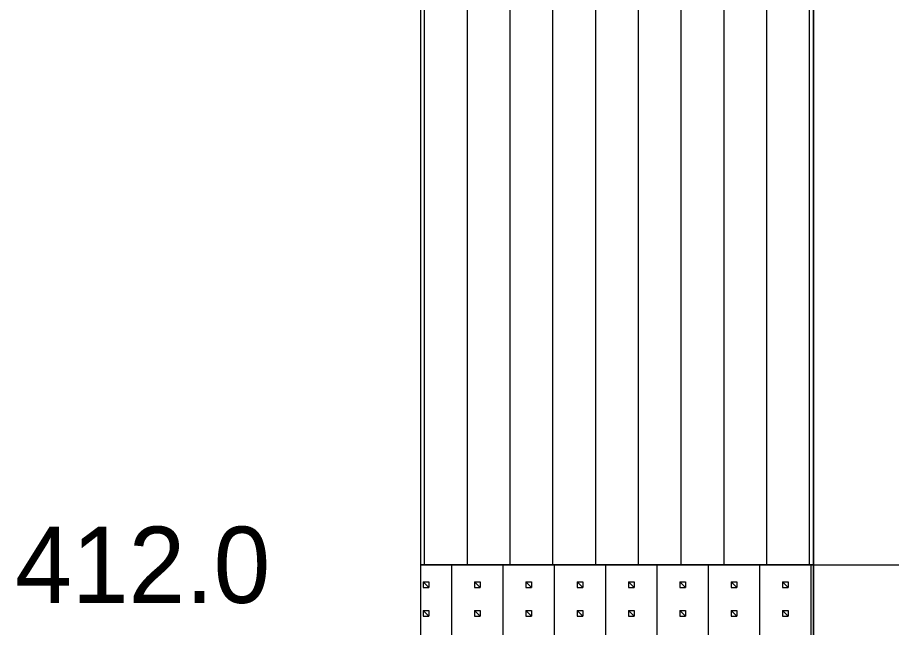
# Model space of a CAD drawing. Extents: x 9422 to 9552, y 6780 to 6860.
# Drawn here: x 9512.845 to 9515.399, y 6826.785 to 6828.568 of the extents above; entities that cross this region are included whole.
import ezdxf

# ---------------------------------------------------------------- set-up
doc = ezdxf.new("R2010")
doc.units = 0
doc.layers.add('7', color=7, linetype='Continuous')
doc.layers.add('8', color=7, linetype='Continuous')

msp = doc.modelspace()

# ---------------------------------------------------------------- linework, layer by layer
at = {"layer": '7'}
for p, q in [((9514.0232, 6831.9684), (9514.0232, 6826.9684)), ((9515.1715, 6826.9684), (9515.1715, 6831.9684)), ((9514.0232, 6826.9684), (9515.1715, 6826.9684)), ((9514.0232, 6826.9684), (9514.0232, 6825.1684)), ((9515.1715, 6826.9684), (9514.0232, 6826.9684)), ((9515.1715, 6825.1684), (9515.1715, 6826.9684)), ((9515.1715, 6826.9684), (9526.1141, 6826.9684))]:
    msp.add_line(p, q, dxfattribs=at)
for points in [[(9514.0232, 6850.4861), (9514.0232, 6821.9406)], [(9515.1715, 6850.4861), (9515.1715, 6821.9406)]]:
    msp.add_lwpolyline(points, dxfattribs=at)
at = {"layer": '8'}
for p, q in [((9514.0348, 6828.4684), (9514.0348, 6828.7184)), ((9514.1598, 6828.4684), (9514.1598, 6828.7184)), ((9514.2848, 6828.4684), (9514.2848, 6828.7184)), ((9514.4098, 6828.4684), (9514.4098, 6828.7184)), ((9514.5348, 6828.4684), (9514.5348, 6828.7184)), ((9514.6598, 6828.4684), (9514.6598, 6828.7184)), ((9514.7848, 6828.4684), (9514.7848, 6828.7184)), ((9514.9098, 6828.4684), (9514.9098, 6828.7184)), ((9515.0348, 6828.4684), (9515.0348, 6828.7184)), ((9515.1598, 6828.4684), (9515.1598, 6828.7184)), ((9514.0348, 6828.2184), (9514.0348, 6828.4684)), ((9514.1598, 6828.2184), (9514.1598, 6828.4684)), ((9514.2848, 6828.2184), (9514.2848, 6828.4684)), ((9514.4098, 6828.2184), (9514.4098, 6828.4684)), ((9514.5348, 6828.2184), (9514.5348, 6828.4684)), ((9514.6598, 6828.2184), (9514.6598, 6828.4684)), ((9514.7848, 6828.2184), (9514.7848, 6828.4684)), ((9514.9098, 6828.2184), (9514.9098, 6828.4684)), ((9515.0348, 6828.2184), (9515.0348, 6828.4684)), ((9515.1598, 6828.2184), (9515.1598, 6828.4684)), ((9514.0348, 6827.9684), (9514.0348, 6828.2184)), ((9514.1598, 6827.9684), (9514.1598, 6828.2184)), ((9514.2848, 6827.9684), (9514.2848, 6828.2184)), ((9514.4098, 6827.9684), (9514.4098, 6828.2184)), ((9514.5348, 6827.9684), (9514.5348, 6828.2184)), ((9514.6598, 6827.9684), (9514.6598, 6828.2184)), ((9514.7848, 6827.9684), (9514.7848, 6828.2184)), ((9514.9098, 6827.9684), (9514.9098, 6828.2184)), ((9515.0348, 6827.9684), (9515.0348, 6828.2184)), ((9515.1598, 6827.9684), (9515.1598, 6828.2184)), ((9514.0348, 6827.7184), (9514.0348, 6827.9684)), ((9514.1598, 6827.7184), (9514.1598, 6827.9684)), ((9514.2848, 6827.7184), (9514.2848, 6827.9684)), ((9514.4098, 6827.7184), (9514.4098, 6827.9684)), ((9514.5348, 6827.7184), (9514.5348, 6827.9684)), ((9514.6598, 6827.7184), (9514.6598, 6827.9684)), ((9514.7848, 6827.7184), (9514.7848, 6827.9684)), ((9514.9098, 6827.7184), (9514.9098, 6827.9684)), ((9515.0348, 6827.7184), (9515.0348, 6827.9684)), ((9515.1598, 6827.7184), (9515.1598, 6827.9684)), ((9514.0348, 6827.4684), (9514.0348, 6827.7184)), ((9514.1598, 6827.4684), (9514.1598, 6827.7184)), ((9514.2848, 6827.4684), (9514.2848, 6827.7184)), ((9514.4098, 6827.4684), (9514.4098, 6827.7184)), ((9514.5348, 6827.4684), (9514.5348, 6827.7184)), ((9514.6598, 6827.4684), (9514.6598, 6827.7184)), ((9514.7848, 6827.4684), (9514.7848, 6827.7184)), ((9514.9098, 6827.4684), (9514.9098, 6827.7184)), ((9515.0348, 6827.4684), (9515.0348, 6827.7184)), ((9515.1598, 6827.4684), (9515.1598, 6827.7184)), ((9514.0348, 6827.2184), (9514.0348, 6827.4684)), ((9514.1598, 6827.2184), (9514.1598, 6827.4684)), ((9514.2848, 6827.2184), (9514.2848, 6827.4684)), ((9514.4098, 6827.2184), (9514.4098, 6827.4684)), ((9514.5348, 6827.2184), (9514.5348, 6827.4684)), ((9514.6598, 6827.2184), (9514.6598, 6827.4684)), ((9514.7848, 6827.2184), (9514.7848, 6827.4684)), ((9514.9098, 6827.2184), (9514.9098, 6827.4684)), ((9515.0348, 6827.2184), (9515.0348, 6827.4684)), ((9515.1598, 6827.2184), (9515.1598, 6827.4684)), ((9514.0348, 6826.9684), (9514.0348, 6827.2184)), ((9514.1598, 6826.9684), (9514.1598, 6827.2184)), ((9514.2848, 6826.9684), (9514.2848, 6827.2184)), ((9514.4098, 6826.9684), (9514.4098, 6827.2184)), ((9514.5348, 6826.9684), (9514.5348, 6827.2184)), ((9514.6598, 6826.9684), (9514.6598, 6827.2184)), ((9514.7848, 6826.9684), (9514.7848, 6827.2184)), ((9514.9098, 6826.9684), (9514.9098, 6827.2184)), ((9515.0348, 6826.9684), (9515.0348, 6827.2184)), ((9515.1598, 6826.9684), (9515.1598, 6827.2184)), ((9514.114, 6826.9017), (9514.114, 6826.9684)), ((9514.264, 6826.9017), (9514.264, 6826.9684)), ((9514.414, 6826.9017), (9514.414, 6826.9684)), ((9514.564, 6826.9017), (9514.564, 6826.9684)), ((9514.714, 6826.9017), (9514.714, 6826.9684)), ((9514.864, 6826.9017), (9514.864, 6826.9684)), ((9515.014, 6826.9017), (9515.014, 6826.9684)), ((9515.164, 6826.9017), (9515.164, 6826.9684)), ((9514.114, 6826.8184), (9514.114, 6826.9017)), ((9514.264, 6826.8184), (9514.264, 6826.9017)), ((9514.414, 6826.8184), (9514.414, 6826.9017)), ((9514.564, 6826.8184), (9514.564, 6826.9017)), ((9514.714, 6826.8184), (9514.714, 6826.9017)), ((9514.864, 6826.8184), (9514.864, 6826.9017)), ((9515.014, 6826.8184), (9515.014, 6826.9017)), ((9515.164, 6826.8184), (9515.164, 6826.9017)), ((9514.114, 6826.7351), (9514.114, 6826.8184)), ((9514.264, 6826.7351), (9514.264, 6826.8184)), ((9514.414, 6826.7351), (9514.414, 6826.8184)), ((9514.564, 6826.7351), (9514.564, 6826.8184)), ((9514.714, 6826.7351), (9514.714, 6826.8184)), ((9514.864, 6826.7351), (9514.864, 6826.8184)), ((9515.014, 6826.7351), (9515.014, 6826.8184)), ((9515.164, 6826.7351), (9515.164, 6826.8184))]:
    msp.add_line(p, q, dxfattribs=at)
for points in [[(9514.0306, 6826.9017), (9514.0473, 6826.9017), (9514.0306, 6826.9184)], [(9514.0473, 6826.9184), (9514.0473, 6826.9017), (9514.0306, 6826.9184), (9514.0473, 6826.9184)], [(9514.1806, 6826.9017), (9514.1973, 6826.9017), (9514.1806, 6826.9184)], [(9514.1973, 6826.9184), (9514.1973, 6826.9017), (9514.1806, 6826.9184), (9514.1973, 6826.9184)], [(9514.3306, 6826.9017), (9514.3473, 6826.9017), (9514.3306, 6826.9184)], [(9514.3473, 6826.9184), (9514.3473, 6826.9017), (9514.3306, 6826.9184), (9514.3473, 6826.9184)], [(9514.4806, 6826.9017), (9514.4973, 6826.9017), (9514.4806, 6826.9184)], [(9514.4973, 6826.9184), (9514.4973, 6826.9017), (9514.4806, 6826.9184), (9514.4973, 6826.9184)], [(9514.6306, 6826.9017), (9514.6473, 6826.9017), (9514.6306, 6826.9184)], [(9514.6473, 6826.9184), (9514.6473, 6826.9017), (9514.6306, 6826.9184), (9514.6473, 6826.9184)], [(9514.7806, 6826.9017), (9514.7973, 6826.9017), (9514.7806, 6826.9184)], [(9514.7973, 6826.9184), (9514.7973, 6826.9017), (9514.7806, 6826.9184), (9514.7973, 6826.9184)], [(9514.9306, 6826.9017), (9514.9473, 6826.9017), (9514.9306, 6826.9184)], [(9514.9473, 6826.9184), (9514.9473, 6826.9017), (9514.9306, 6826.9184), (9514.9473, 6826.9184)], [(9515.0806, 6826.9017), (9515.0973, 6826.9017), (9515.0806, 6826.9184)], [(9515.0973, 6826.9184), (9515.0973, 6826.9017), (9515.0806, 6826.9184), (9515.0973, 6826.9184)], [(9514.0306, 6826.8184), (9514.0473, 6826.8184), (9514.0306, 6826.8351)], [(9514.0473, 6826.8351), (9514.0473, 6826.8184), (9514.0306, 6826.8351), (9514.0473, 6826.8351)], [(9514.1806, 6826.8184), (9514.1973, 6826.8184), (9514.1806, 6826.8351)], [(9514.1973, 6826.8351), (9514.1973, 6826.8184), (9514.1806, 6826.8351), (9514.1973, 6826.8351)], [(9514.3306, 6826.8184), (9514.3473, 6826.8184), (9514.3306, 6826.8351)], [(9514.3473, 6826.8351), (9514.3473, 6826.8184), (9514.3306, 6826.8351), (9514.3473, 6826.8351)], [(9514.4806, 6826.8184), (9514.4973, 6826.8184), (9514.4806, 6826.8351)], [(9514.4973, 6826.8351), (9514.4973, 6826.8184), (9514.4806, 6826.8351), (9514.4973, 6826.8351)], [(9514.6306, 6826.8184), (9514.6473, 6826.8184), (9514.6306, 6826.8351)], [(9514.6473, 6826.8351), (9514.6473, 6826.8184), (9514.6306, 6826.8351), (9514.6473, 6826.8351)], [(9514.7806, 6826.8184), (9514.7973, 6826.8184), (9514.7806, 6826.8351)], [(9514.7973, 6826.8351), (9514.7973, 6826.8184), (9514.7806, 6826.8351), (9514.7973, 6826.8351)], [(9514.9306, 6826.8184), (9514.9473, 6826.8184), (9514.9306, 6826.8351)], [(9514.9473, 6826.8351), (9514.9473, 6826.8184), (9514.9306, 6826.8351), (9514.9473, 6826.8351)], [(9515.0806, 6826.8184), (9515.0973, 6826.8184), (9515.0806, 6826.8351)], [(9515.0973, 6826.8351), (9515.0973, 6826.8184), (9515.0806, 6826.8351), (9515.0973, 6826.8351)]]:
    msp.add_lwpolyline(points, close=True, dxfattribs=at)

# ---------------------------------------------------------------- texts
at = {"layer": '7'}
msp.add_text('412.0', height=0.2228, dxfattribs=at).set_placement((9512.8384, 6826.857))

doc.saveas('drawing.dxf')
